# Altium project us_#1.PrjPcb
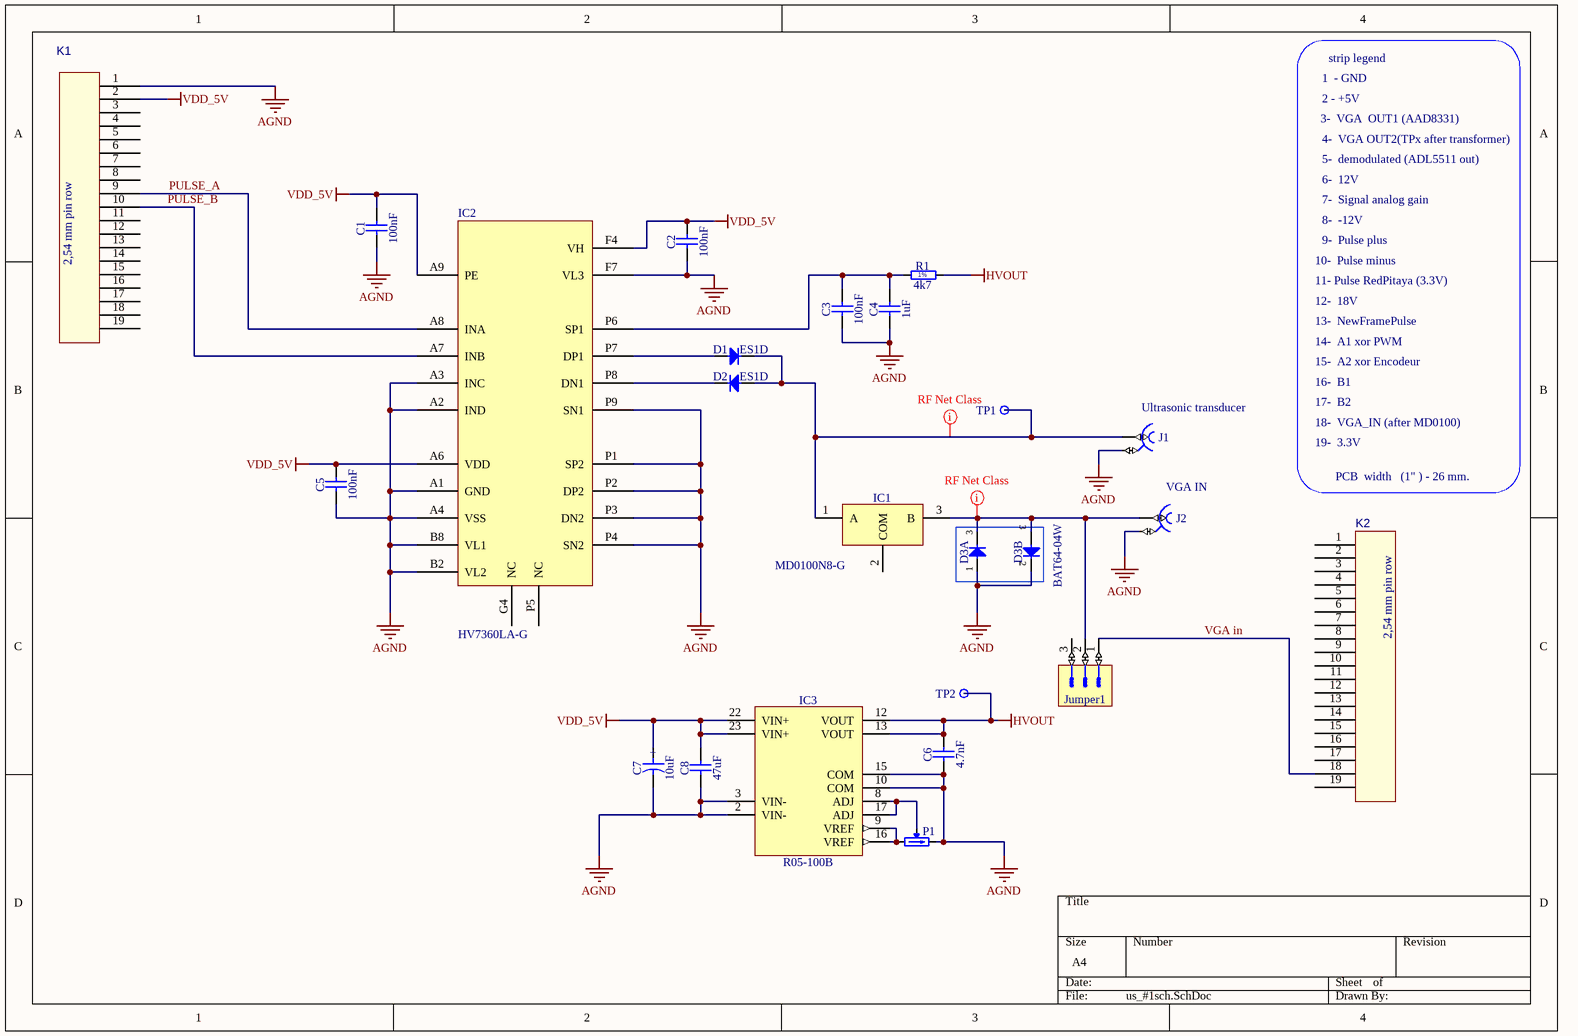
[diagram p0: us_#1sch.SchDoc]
1 sheet, 23 parts. Net scope: global (net labels, ports and power ports of the same name join across sheets).
Board file: us_#1.PcbDoc

## Sheet us_#1sch.SchDoc: #1 extension. DC/DC, HV pulser, MD0100,VGA
size A4

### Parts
C1  100nF  [CAPC1608X87N]
C2  100nF  [CAPC1608X87N]
C3  100nF  [CAPC1608X87N]
C4  1uF  [CAPC5650X165N]
C5  100nF  [CAPC1608X87N]
C6  4.7nF  [CAPC2012X110N]
C7  10uF  [CAPMP3528X210N]
C8  47uF  [CAPC3216X180N]
D1  ES1D  [DIOM5027X244N]
D2  ES1D  [DIOM5027X244N]
D3  BAT64-04W  [SOT65P210X100-3N]  (parts A,B of 2)
IC1  MD0100N8-G  [SOT89]
IC2  HV7360LA-G  [HV7360_BGA]
IC3  R05-100B  [PWS_RECOM_R05-100B]
J1  SMA  [AMPHENOL_132357-11]  (value not drawn)
J2  SMA  [AMPHENOL_132357-11]  (value not drawn)
Jumper1  (no value)  [SULLINS_GRPB031VWVN]
K1  PLS_2.54mm-19  [PLS_2.54mm-19]  (value not drawn)
K2  PLS_2.54mm-19  [PLS_2.54mm-19]  (value not drawn)
P1  5k  [TRIM_BOURNS_3223W]  (value not drawn)
R1  4k7  [RESC3216X65N]
TP1  Test Point  [NICOMATIC_C12000B]  (value not drawn)
TP2  Test Point  [NICOMATIC_C12000B]  (value not drawn)

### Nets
AGND: C1.1 C2.1 C3.1 C4.1 C5.1 C6.1 C7.2 C8.1 D3.1(A) D3.2(C) IC2.A1(GND) IC2.A2(IND) IC2.A3(INC) IC2.A4(VSS) IC2.B2(VL2) IC2.B8(VL1) IC2.F7(VL3) IC2.P1(SP2) IC2.P2(DP2) IC2.P3(DN2) IC2.P4(SN2) IC2.P9(SN1) IC3.2(VIN-) IC3.3(VIN-) IC3.10(COM) IC3.15(COM) J1.2 J2.2 K1.1 P1.3(CW)
HVOUT: C6.2 IC3.12(VOUT) IC3.13(VOUT) R1.2 TP2.1
VDD_5V: C1.2 C2.2 C5.2 C7.1 C8.2 IC2.A6(VDD) IC2.A9(PE) IC2.F4(VH) IC3.22(VIN+) IC3.23(VIN+) K1.2
PULSE_A: IC2.A8(INA) K1.9
PULSE_B: IC2.A7(INB) K1.10
VGA in: Jumper1.1 K2.18
NetC3_2: C3.2 C4.2 IC2.P6(SP1) R1.1
NetD1_1: D1.1(C) D2.2(A) IC1.1(A) J1.1 TP1.1
NetD1_2: D1.2(A) IC2.P7(DP1)
NetD2_1: D2.1(C) IC2.P8(DN1)
NetD3_3: D3.3(COMAC) IC1.3(B) J2.1 Jumper1.2
NetIC3_8: IC3.8(ADJ) IC3.17(ADJ) P1.2(W)
NetIC3_9: IC3.9(VREF) IC3.16(VREF) P1.1(CCW)

Not connected (* = marked no-connect by the designer): IC1 2(COM); IC2 G4(NC) P5(NC); Jumper1 3; K1 3 4 5 6 7 8 11 12 13 14 15 16 17 18 19; K2 1 2 3 4 5 6 7 8 9 10 11 12 13 14 15 16 17 19

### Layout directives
net class RF: NetD1_1, NetD3_3

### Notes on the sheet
- 2 - +5V
- 1  - GND
- strip legend
- 3-  VGA  OUT1 (AAD8331)
- 4-  VGA OUT2(TPx after transformer)
- 5-  demodulated (ADL5511 out)
- 6-  12V
- 7-  Signal analog gain
- 8-  -12V
- 9-  Pulse plus
- 10-  Pulse minus
- 11- Pulse RedPitaya (3.3V)
- 12-  18V
- 13-  NewFramePulse
- 14-  A1 xor PWM
- 15-  A2 xor Encodeur
- 16-  B1
- (near J1) Ultrasonic transducer
- 17-  B2
- 18-  VGA_IN (after MD0100)
- 19-  3.3V
- VGA IN
- PCB  width   (1" ) - 26 mm.

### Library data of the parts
C1-C3 C5 = CC0603_100NF_50V_10%_X7R: Non-polarised capacitor; Part Description: SMD Multilayer Chip Ceramic Capacitor; Manufacturer: GENERIC; Manufacturer1 Part Number: 223858615649; Voltage: 50V; TC: X7R; Tolerance: ±10%; Table: Capacitors SMD
C4 = CC2220_1UF_200V_10%_X7R: Non-polarised capacitor; Part Description: SMD Ceramic Chip Capacitor; Manufacturer: GENERIC; Manufacturer1 Part Number: C2220X105K2RAC; Voltage: 200V; TC: X7R; Tolerance: ±10%; Table: Capacitors SMD
C6 = CC0805_4.7NF_250V_10%_X7R: Non-polarised capacitor; Part Description: SMD Multilayer Chip Ceramic Capacitor; Manufacturer: GENERIC; Manufacturer1 Part Number: GRM21AR72E472KW01D; Voltage: 250V; TC: X7R; Tolerance: ±10%; Table: Capacitors SMD
C7 = CTE3528-21_10UF_16V_10%_LESR0800: Polarised capacitor; Part Description: Low ESR 0R8 Solid Tantalum Chip Capacitor; Manufacturer: GENERIC; Manufacturer1 Part Number: TPSB106K016R0800; Voltage: 16V; Tolerance: ±10%; Table: Capacitors SMD
C8 = CC1206_47UF_25V_20%_X5R: Non-polarised capacitor; Part Description: SMD Multilayer Chip Ceramic Capacitor; Manufacturer: TDK; Manufacturer Part Number: C3216X5R1E476M160AC; Voltage: 25V; TC: X5R; Tolerance: ±20%; Table: Capacitors SMD
D1 D2 = ES1D: Diode; Part Description: Fast Rectifier; Manufacturer: FAIRCHILD SEMICONDUCTOR; Voltage: 200V; Power: 1A; Table: Diodes
D3 = BAT64-04W: Serial Diode; Part Description: Silicon Schottky Double Diode; Manufacturer: INFINEON; Voltage: 40V; Power: 250mW; Table: Diodes
IC1 = MD0100N8-G: 3-Ultra-Sound HV Switch 1=A 2=COM 3=B; Manufacturer: Supertex inc.; Table: Analog & Interface
IC2 = HV7360_BGA: Part Description: High Speed, ±100V 2.5A Two or Three Level Ultrasound Pulser; Manufacturer: Supertex inc.; Table: Analog & Interface
IC3 = PWS_RECOM_R05-100B: Power Supply; Part Description: +5VDC to +55-135VDC 5W Power Supply; Manufacturer: RECOM POWER; Table: Power Supplies
J1 J2 = AMPHENOL_132357-11: Part Description: SMA End Launch Jack for 1.58mm PCB, 50 Ohm, Flat Tab Contact
Jumper1 = Connector 3 Male: Part Description: 3 Contact 0.5" Pitch Single-In-Line Vertical Header; Manufacturer: SULLINS; Manufacturer Part Number: GRPB031VWVN; Table: Miscellaneous
P1 = TRIM_11T_5K_BOURNS_3223W-1-502E: Trimming Potentiometer; Part Description: 11 Turns SMD Trimpot® Trimming Potentiometer (Top Adjust); Manufacturer: BOURNS; Power: 0.125W; TC: ±100ppm/°C; Tolerance: ±20%; Table: Potentiometers SMD
R1 = R1206_4K7_1%_0.25W_100PPM: Resistor - 1%; Part Description: General Purpose Thick Film Chip Resistor; Manufacturer: GENERIC; Manufacturer1 Part Number: NRC12F4701TRF; Power: 0.25W; TC: ±100ppm/°C; Table: Resistors SMD
TP1 TP2 = NICOMATIC_C12000B: Part Description: SMD Test Point; Table: Miscellaneous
